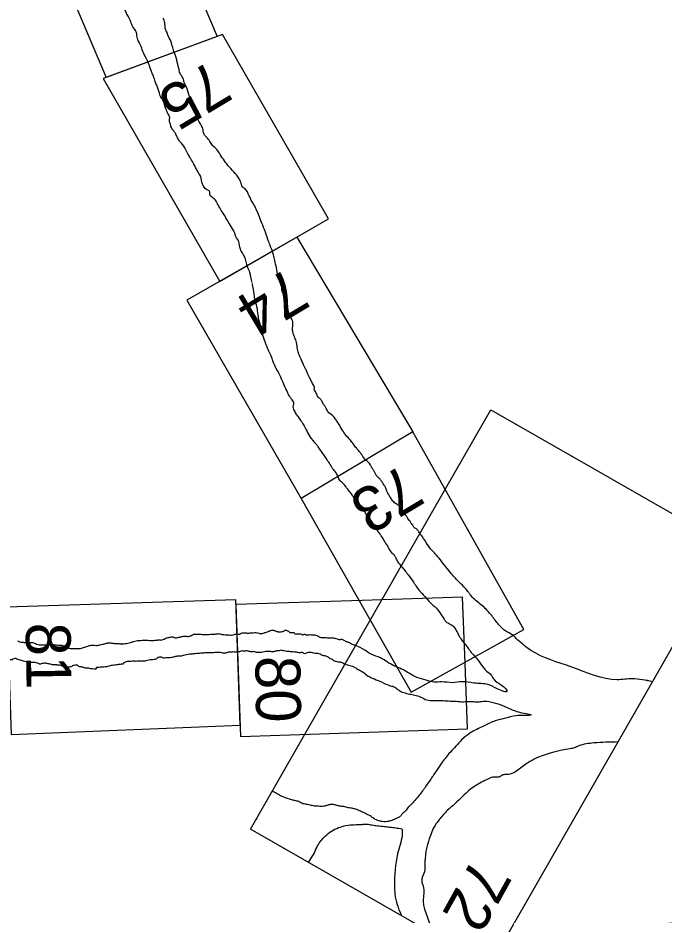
# Model space of a CAD drawing. Extents: x 3930721 to 3950824, y 220441 to 242861.
# Drawn here: x 3935065 to 3935907, y 230142 to 231312 of the extents above; entities that cross this region are included whole.
import ezdxf

# ---------------------------------------------------------------- set-up
doc = ezdxf.new("R2010")
doc.units = 0
doc.layers.add('V-ANNO-NPLT', color=7, linetype='Continuous')
doc.layers.add('V-GRID-MAJR', color=7, linetype='Continuous')

msp = doc.modelspace()

# ---------------------------------------------------------------- linework, layer by layer
at = {"layer": 'V-ANNO-NPLT'}
for p, q in [((3935579.3, 230772), (3935433.9, 230684.9)), ((3935376.4, 230266.9), (3935375.4, 230266.7)), ((3935443.6, 230210.4), (3935451.1, 230222.8))]:
    msp.add_line(p, q, dxfattribs=at)
for points in [[(3935207.9, 231561.8), (3935324.4, 231287.7)], [(3935065.5, 231504.1), (3935179.6, 231234.3)], [(3935331.3, 231290.3), (3935176, 231232.9), (3935327.7, 230968.2)], [(3935469.3, 231049.6), (3935331.3, 231290.3)], [(3935324.4, 231287.7), (3935179.6, 231234.3)], [(3935327.7, 230968.2), (3935469.3, 231049.6)], [(3935428.2, 231026), (3935284.8, 230943.6), (3935433.9, 230684.9)], [(3935428.2, 231026), (3935579.3, 230772)], [(3935681.1, 230800.8), (3935992.7, 230622.2), (3935679.4, 230075.2), (3935367.7, 230253.6)], [(3935622.6, 230698.5), (3935681.1, 230800.8)], [(3935579.3, 230772), (3935433.9, 230684.9), (3935577.3, 230432.3), (3935724.2, 230514.3)], [(3935724.2, 230514.3), (3935579.3, 230772)], [(3935436.6, 230373.8), (3935622.6, 230698.5)], [(3935050.4, 230543.6), (3935348.6, 230553.2)], [(3935354.5, 230389.5), (3935348.6, 230553.2)], [(3935513.5, 230552.1), (3935348.9, 230546.9)], [(3935644.3, 230556.3), (3935513.5, 230552.1)], [(3935647.5, 230470.2), (3935644.3, 230556.3)], [(3935050.4, 230543.6), (3935056, 230377.1), (3935354.5, 230389.5)], [(3935348.9, 230546.9), (3935355, 230374.6), (3935650.8, 230384.6), (3935647.5, 230470.2)], [(3935367.7, 230253.6), (3935436.6, 230373.8)]]:
    msp.add_lwpolyline(points, dxfattribs=at)
for points in [[(3935247.5, 231218.9), (3935243.8, 231229), (3935241.4, 231236), (3935239.2, 231240.8), (3935236, 231249.9), (3935231.5, 231260.2), (3935227.6, 231268.1), (3935224.5, 231276.5), (3935221.6, 231281.8), (3935219.9, 231288.4), (3935218.9, 231293.5), (3935214.7, 231300.1), (3935211.7, 231306.9), (3935208.3, 231314), (3935205.3, 231319.9), (3935201.5, 231328.1), (3935199.8, 231331.7), (3935196.4, 231337.4)], [(3935253.6, 231311.8), (3935255.7, 231305.8), (3935256, 231301.6), (3935257.1, 231296.5), (3935259.3, 231291.6)], [(3935271.5, 231258.5), (3935267.1, 231271.3), (3935264.7, 231279.3), (3935261.1, 231287.6), (3935259.3, 231291.6)], [(3935328.2, 231133.7), (3935324.1, 231140), (3935318.4, 231145.4), (3935315, 231150.7), (3935310.3, 231156.3), (3935307.4, 231159.6), (3935306.1, 231165.7), (3935305.1, 231168.7), (3935299.8, 231178.8), (3935296.1, 231188.3), (3935294.6, 231193.2), (3935291.8, 231199.4), (3935288.7, 231207.7), (3935287, 231213.2), (3935282.8, 231225), (3935281.1, 231228.4), (3935280.5, 231232.1), (3935276.7, 231238), (3935274.7, 231244.8), (3935272.4, 231253.9), (3935271.5, 231258.5)], [(3935302.9, 231105.2), (3935298.5, 231112.7), (3935294.1, 231121), (3935290.1, 231127.9), (3935287.3, 231132.8), (3935283.5, 231139.9), (3935277.7, 231148.6), (3935274.8, 231152), (3935272.2, 231156.4), (3935269.9, 231161.4), (3935265.5, 231167.6), (3935264.2, 231170.1), (3935263.1, 231174.4), (3935262.1, 231178.2), (3935262.5, 231181.6), (3935260.1, 231187.1), (3935258.2, 231191.4), (3935255.7, 231199.4), (3935254.5, 231203.4), (3935251.8, 231207.1), (3935249.3, 231213.8), (3935247.5, 231218.9)], [(3935396.3, 231007.8), (3935390.6, 231022.7), (3935386, 231035.7), (3935381.5, 231047), (3935377.3, 231058.1), (3935370.8, 231070.6), (3935366.1, 231079.9), (3935360.3, 231089.2), (3935357.4, 231091.5), (3935355.2, 231097.7), (3935353.6, 231101.3), (3935347.9, 231109), (3935340.1, 231117.5), (3935328.2, 231133.7)], [(3935370.1, 230966.6), (3935368.2, 230974.2), (3935367.1, 230979.7), (3935363.9, 230987), (3935360.2, 231000.5), (3935354.7, 231010.3), (3935352.5, 231020.2), (3935348.9, 231026.7), (3935347.3, 231031.3), (3935345.9, 231034.3), (3935340.3, 231043.1), (3935335.9, 231051.1), (3935330.9, 231058.9), (3935326.7, 231066.2), (3935323.1, 231072.7), (3935318.4, 231077.6), (3935314.8, 231081.4), (3935315, 231084.5), (3935313.9, 231086.3), (3935310.7, 231088.2), (3935302.9, 231105.2)], [(3935438.1, 230856.9), (3935433.7, 230866.7), (3935431, 230873.4), (3935429.1, 230879.6), (3935427.8, 230888.6), (3935425.5, 230895), (3935422.9, 230902.7), (3935422.9, 230909.4), (3935422.5, 230917.3), (3935419, 230923.5), (3935416.4, 230933.7), (3935413.5, 230942.6), (3935412.1, 230950.6), (3935409.6, 230954.1), (3935408.7, 230960.3), (3935403.7, 230975.1), (3935401.6, 230986.1), (3935399.5, 230995.5), (3935397.7, 231002.7), (3935396.3, 231007.8)], [(3935416.9, 230821.7), (3935409.5, 230838.2), (3935404.9, 230848.5), (3935400.4, 230856.4), (3935396.7, 230865.7), (3935393.4, 230873.8), (3935390, 230881), (3935387.9, 230886.8), (3935384.5, 230896.6), (3935381.3, 230909.2), (3935377.7, 230924.6), (3935376.3, 230935.2), (3935373.3, 230945.6), (3935372.5, 230952.8), (3935370.8, 230962), (3935370.3, 230965.4)], [(3935505.8, 230750.9), (3935502, 230755.8), (3935498, 230761.2), (3935492.1, 230767.7), (3935487.4, 230774.7), (3935482.3, 230783.2), (3935479.4, 230787.5), (3935476.1, 230792), (3935470.1, 230796.9), (3935465.6, 230804.2), (3935461.7, 230810.4), (3935459.4, 230814.3), (3935456, 230817.2), (3935453.6, 230822.4), (3935451, 230827.4), (3935451.2, 230829.8), (3935448.8, 230835), (3935446.3, 230839.9), (3935443.1, 230846.1), (3935441.2, 230850.6), (3935439.3, 230854.7), (3935438.1, 230856.9)], [(3935434.8, 230784.9), (3935433.8, 230786.4), (3935430.4, 230791.4), (3935427.1, 230795.9), (3935424.4, 230801.3), (3935423.6, 230804.8), (3935424.5, 230808.5), (3935422.1, 230813.7), (3935419.4, 230817), (3935416.9, 230821.7)], [(3935434.8, 230784.9), (3935440.4, 230774.4), (3935445.1, 230766), (3935453.7, 230755.5)], [(3935481.9, 230713.7), (3935479.3, 230718.6), (3935475.9, 230722.7), (3935471.8, 230729.4), (3935467.7, 230735.3), (3935464.2, 230740.7), (3935460.3, 230746.4), (3935455.9, 230752.5), (3935453.8, 230755.4), (3935453.7, 230755.5)], [(3935588.6, 230639.2), (3935587.2, 230641.5), (3935585.1, 230644.4), (3935583.1, 230646), (3935581.2, 230647.1), (3935579.2, 230650.1), (3935577.5, 230652.3), (3935575.3, 230655.7), (3935573.4, 230658.2), (3935571.1, 230662.1), (3935568.6, 230664.4), (3935565.8, 230669.5), (3935563.5, 230672.1), (3935560.7, 230675.9), (3935556.8, 230678.6), (3935552.6, 230682.9), (3935549.6, 230687.2), (3935546.9, 230691.8), (3935545, 230695.8), (3935543.8, 230699.5), (3935541.2, 230703.6), (3935538.6, 230707.7), (3935535.9, 230711), (3935533.1, 230713.5), (3935530.9, 230717), (3935528.9, 230720.7), (3935526.7, 230724.1), (3935524.4, 230728.1), (3935520.9, 230732.7), (3935516.7, 230736.5), (3935512.2, 230743), (3935509, 230747), (3935505.8, 230750.9)], [(3935564.3, 230596.9), (3935558.8, 230604.6), (3935556.1, 230610), (3935551.4, 230615), (3935547.4, 230621.6), (3935542.8, 230629), (3935538.3, 230636.3), (3935535.5, 230640.1), (3935530.7, 230647.7), (3935526.7, 230653.8), (3935523, 230659), (3935519.4, 230662.9), (3935517, 230667.3), (3935514.8, 230671.5), (3935513, 230674.8), (3935508.7, 230676.9), (3935506.4, 230680.8), (3935503.7, 230684.1), (3935501.5, 230687.5), (3935498.7, 230692.1), (3935494.5, 230697.2), (3935489, 230704.3), (3935484.6, 230708.2), (3935481.9, 230713.7)], [(3935716.3, 230500.1), (3935708.8, 230507.3), (3935700.8, 230512), (3935691.4, 230520.4), (3935682.2, 230532.2), (3935670.6, 230544.5), (3935656.9, 230556.3), (3935647.7, 230568.1), (3935640.2, 230575.3), (3935629.8, 230586.8), (3935622.6, 230595.7), (3935615.4, 230604.9), (3935608.6, 230613), (3935604.8, 230617.1), (3935598.1, 230625.6), (3935593.5, 230632.9), (3935588.6, 230639.2)], [(3935564.3, 230596.9), (3935573.3, 230585.5), (3935580.2, 230575.9), (3935589, 230563.5), (3935596.9, 230555.2), (3935603.8, 230547.4), (3935608.4, 230543.5), (3935614.4, 230536.4), (3935620.2, 230527.5), (3935622.7, 230524.2), (3935627.2, 230521.7), (3935632.8, 230517.5), (3935637.5, 230510.2), (3935639.9, 230505.2), (3935644.3, 230498.9), (3935651.9, 230489), (3935656.7, 230482.8), (3935663.4, 230475.3), (3935670.9, 230465), (3935677, 230458.6), (3935677.9, 230458.1), (3935685, 230449.3), (3935693.6, 230442.5), (3935699.2, 230438.2), (3935702, 230433.8), (3935689.3, 230436.9), (3935677.2, 230442.3), (3935659, 230444.3), (3935644.1, 230445.9), (3935630.9, 230444.7), (3935617, 230445.8), (3935607, 230445.5), (3935596.7, 230448), (3935584.5, 230451.7), (3935564.8, 230462.6), (3935554.7, 230466.8), (3935546.1, 230471.8), (3935537.4, 230477.1), (3935525.3, 230481.8), (3935516.7, 230487.2), (3935504.6, 230493.6)], [(3935271.4, 230502.9), (3935270.7, 230502.9), (3935269, 230503.3), (3935268.1, 230503.8), (3935265.8, 230504.3), (3935263.2, 230503.9), (3935261.1, 230503.4), (3935258.8, 230503), (3935257.2, 230502.2), (3935255.2, 230501.3), (3935253.1, 230500.8), (3935251.5, 230500), (3935249.8, 230500.2), (3935247.5, 230500.1), (3935245.7, 230500), (3935242.8, 230499.7), (3935240.2, 230499.2), (3935238.2, 230499.2), (3935236.5, 230499.4), (3935232.4, 230499.8), (3935229.7, 230499.6), (3935226.7, 230500)], [(3935279.7, 230504.9), (3935278.1, 230504.4), (3935276, 230504), (3935273.6, 230503.5), (3935271.4, 230502.9)], [(3935288.6, 230505.6), (3935286.4, 230504.6), (3935284.8, 230504.9), (3935282, 230505.1), (3935279.7, 230504.9)], [(3935381.6, 230508.3), (3935381.4, 230508.2), (3935380, 230508.7), (3935378.9, 230509.1), (3935375.3, 230509.6), (3935371.4, 230509.5), (3935368.3, 230509.4), (3935365.8, 230509), (3935363.7, 230509.1), (3935358.8, 230509.3), (3935355.6, 230509), (3935353.2, 230507.7), (3935350.8, 230508), (3935348.5, 230507.7), (3935347.3, 230507.6), (3935344.8, 230506.6), (3935341.7, 230506.5), (3935338.8, 230506.8), (3935331.1, 230507.3), (3935326.2, 230508.3), (3935320.8, 230507.7), (3935317.5, 230507.7), (3935314, 230507.3), (3935307.1, 230507.3), (3935303, 230507.5), (3935299.8, 230507.7), (3935294.5, 230507.6), (3935293, 230507.4), (3935291.4, 230506.1), (3935288.6, 230505.6)], [(3935395, 230512.8), (3935392, 230511.7), (3935389.3, 230510.5), (3935385.2, 230509.3), (3935382.7, 230508.6), (3935381.6, 230508.3)], [(3935418.4, 230510.9), (3935416.8, 230511.8), (3935415.8, 230512.4), (3935414.1, 230513.1), (3935412.8, 230512.8), (3935411.1, 230511.9), (3935409.7, 230511.3), (3935408.6, 230510.9), (3935405.7, 230510.7), (3935404.1, 230510.8), (3935402.7, 230511.3), (3935400.9, 230511.9), (3935399.5, 230512.4), (3935398.1, 230512.7), (3935396.6, 230513.1), (3935395, 230512.8)], [(3935442.7, 230506.8), (3935441.8, 230506.6), (3935440.6, 230506.8), (3935439.4, 230507.2), (3935437.6, 230507.5), (3935437.3, 230507.4), (3935436, 230507.1), (3935435.6, 230506.8), (3935434.7, 230507.6), (3935431.8, 230507.9), (3935429.5, 230508.2), (3935425.4, 230508.7), (3935424.8, 230509.6), (3935423.5, 230509.8), (3935421.5, 230509.7), (3935420.1, 230509.7), (3935419.5, 230510), (3935418.4, 230510.9)], [(3935453.5, 230506.5), (3935451.1, 230506.7), (3935448.3, 230506.7), (3935445.2, 230507), (3935442.7, 230506.8)], [(3935504.6, 230493.6), (3935499.4, 230495.2), (3935496.9, 230496.6), (3935495, 230497.5), (3935493.1, 230498.1), (3935491.5, 230499.1), (3935489.7, 230499.8), (3935488, 230500.6), (3935485.7, 230500.9), (3935483.6, 230500.7), (3935481.1, 230501.7), (3935478.2, 230502.3), (3935476.2, 230502.7), (3935473.2, 230502.8), (3935470.8, 230502.9), (3935469.1, 230502.8), (3935466, 230503.2), (3935463.8, 230503.2), (3935458.5, 230503.6), (3935455.5, 230505.4), (3935453.5, 230506.5)], [(3935138.4, 230488.8), (3935134.3, 230488.9), (3935130.1, 230489.7), (3935127.3, 230490.5), (3935123.4, 230492.8), (3935118.7, 230493.3), (3935115.1, 230493.6), (3935112.9, 230493.8), (3935109, 230494.1), (3935103, 230493.5), (3935099.9, 230493.7), (3935096.5, 230493.9), (3935093, 230493.9), (3935089, 230494.6), (3935086, 230496.1), (3935082.6, 230496.7), (3935079.4, 230496.8), (3935076.1, 230497), (3935073.3, 230496.9), (3935070.5, 230497.1), (3935067.1, 230497.7), (3935065.3, 230498.7), (3935064.8, 230498.8)], [(3935199.6, 230495.3), (3935198.9, 230495.2), (3935194.4, 230495.6), (3935192, 230495.5), (3935186.3, 230496.3), (3935181.6, 230496.2), (3935177.1, 230495.1), (3935171.5, 230493.7), (3935166.4, 230492.9), (3935162.8, 230493.3), (3935158.5, 230493), (3935154.3, 230491.4), (3935151, 230490.7), (3935145.9, 230489.1), (3935142, 230489), (3935140.2, 230488.9), (3935138.4, 230488.8)], [(3935212.4, 230497.2), (3935209.9, 230496.3), (3935206.2, 230495.5), (3935202.8, 230495), (3935200.7, 230494.9), (3935199.5, 230495.3)], [(3935226.7, 230500), (3935223.3, 230499.2), (3935220.7, 230499.3), (3935217, 230498.5), (3935213.9, 230497.7), (3935212.4, 230497.2)], [(3935891.9, 230445.9), (3935865.5, 230449.8), (3935845.7, 230448.6), (3935786.8, 230465), (3935733.4, 230486.8), (3935716.3, 230500.1)], [(3935891.8, 230446), (3935865.5, 230449.8), (3935845.7, 230448.6), (3935786.8, 230465), (3935733.4, 230486.8), (3935716.3, 230500.1)], [(3935306.6, 230483.2), (3935299.7, 230482.9), (3935295.6, 230482.4), (3935293.1, 230482.2), (3935288.3, 230481.9), (3935284.5, 230480.9), (3935280.4, 230480.4), (3935278.6, 230479.8), (3935273.6, 230479.3), (3935269, 230478.5), (3935264.9, 230477.4), (3935261.2, 230477.1), (3935257.7, 230477.1), (3935254.3, 230476.8), (3935252.7, 230477.5), (3935248.9, 230478), (3935246.3, 230476.6), (3935242.3, 230474.9), (3935238.9, 230474.6), (3935235.2, 230474.2), (3935231.4, 230473.2), (3935226.3, 230473), (3935221.8, 230472.8), (3935218.2, 230472.6), (3935213.6, 230472.8), (3935210.1, 230472.2), (3935207, 230472.4), (3935204.4, 230471.5)], [(3935399.8, 230485.6), (3935395.9, 230485), (3935394.3, 230485.4), (3935392.5, 230485.3), (3935389.5, 230485.6), (3935387.7, 230485.5), (3935383.9, 230484.6), (3935377.5, 230484), (3935375.5, 230484.1), (3935373.5, 230485.2), (3935371, 230485), (3935367.9, 230485.1), (3935365.8, 230485.5), (3935363.7, 230486.4), (3935360.8, 230485.9), (3935358.7, 230485.9), (3935356.8, 230486.1), (3935353.3, 230485.1), (3935350.2, 230484.8), (3935348.1, 230484.7), (3935344.9, 230484.8), (3935343.1, 230484.7), (3935338.8, 230484.4), (3935334.6, 230483.1), (3935330.6, 230483.7), (3935326.5, 230484.2), (3935321.4, 230484), (3935318, 230483.7), (3935313.3, 230483.6), (3935309, 230483.8), (3935306.6, 230483.2)], [(3935490.8, 230468.9), (3935488.2, 230470.2), (3935484.5, 230471.5), (3935482.3, 230471.7), (3935479.7, 230472.3), (3935477.6, 230472.7), (3935475.6, 230474.2), (3935473.4, 230475.5), (3935471.2, 230476.5), (3935468.3, 230478.6), (3935466.2, 230479.5), (3935464.1, 230479.9), (3935461.6, 230480.2), (3935458.5, 230481.8), (3935455.4, 230483), (3935452.2, 230482.9), (3935448.9, 230483.7), (3935445.3, 230484.1), (3935442.9, 230484.1), (3935440.2, 230483.4), (3935438.5, 230482.6), (3935436.5, 230483.5), (3935434.8, 230484.2), (3935432.9, 230483.9), (3935431.1, 230483.8), (3935429, 230484.2), (3935426.5, 230484.5), (3935423.5, 230484.8), (3935421.5, 230484.9), (3935418.8, 230485.3), (3935411.7, 230486.1), (3935406.4, 230486.9), (3935403.8, 230486.1), (3935401.9, 230486.3), (3935399.8, 230485.6)], [(3935114.6, 230468), (3935110.4, 230468), (3935106.3, 230469), (3935101.8, 230469.9), (3935097.4, 230469.9), (3935092.9, 230469.1), (3935090.1, 230470.4), (3935084.3, 230471), (3935080.4, 230471.3), (3935075.4, 230471.9), (3935072.1, 230472.7), (3935066.5, 230474.6), (3935063.3, 230475.6), (3935060.5, 230476.4), (3935058.2, 230475.4), (3935056.1, 230474.4), (3935054.3, 230474.8), (3935053.5, 230475)], [(3935204.4, 230471.5), (3935202.8, 230470.5), (3935202.2, 230469.6), (3935197.9, 230468.7), (3935193.3, 230467.9), (3935186.3, 230467.1), (3935180.5, 230465.6), (3935171.8, 230464.9), (3935168.8, 230464.7), (3935167.2, 230464.5), (3935166.6, 230463.6), (3935166.6, 230463), (3935164, 230462.6), (3935160.3, 230462.7), (3935155.9, 230463.9), (3935152.4, 230463.9), (3935148.2, 230465.2), (3935144.2, 230465.9), (3935142.2, 230467.4), (3935138.8, 230467.6), (3935135.9, 230466.7), (3935133.7, 230465.4), (3935131, 230464.9), (3935126.7, 230465.5), (3935122.6, 230466.5), (3935118.8, 230467.5), (3935116, 230467.8), (3935114.6, 230468)], [(3935490.8, 230468.9), (3935503.8, 230464.7), (3935508.5, 230461.9), (3935514.5, 230458.4), (3935521.4, 230453.3), (3935525.6, 230451.2), (3935529.4, 230449.6), (3935538.6, 230445.7), (3935550, 230440.8), (3935556.1, 230438.9), (3935560.4, 230435.5), (3935575.1, 230430), (3935581.8, 230428.7), (3935589.9, 230426), (3935597.6, 230422.2), (3935606.2, 230421.6), (3935611.7, 230421.6), (3935618.7, 230421.4), (3935628.1, 230420.8), (3935636.3, 230420.6), (3935642.9, 230419.9), (3935652.4, 230420.3), (3935660.3, 230420), (3935666.2, 230420), (3935672.5, 230420.8), (3935685.5, 230418.4), (3935698.4, 230414.3), (3935706.1, 230410.6), (3935717.3, 230406.6), (3935727.2, 230404.6), (3935733.8, 230402.9), (3935723.9, 230401.8), (3935713.9, 230401.7), (3935698.6, 230398), (3935686.9, 230395), (3935672.2, 230388.5), (3935653.8, 230378.8), (3935643.4, 230370.5), (3935635.5, 230361.8), (3935628.3, 230354.3), (3935617.6, 230340.9), (3935610.6, 230330.7), (3935602.8, 230319.1), (3935595.4, 230308.2), (3935586.5, 230296.4), (3935580.4, 230289.2), (3935576.7, 230285.4)], [(3935846.8, 230367.5), (3935815.4, 230366.1), (3935795.6, 230362.2), (3935790, 230359.8), (3935784.1, 230358.5), (3935743.2, 230347.4), (3935732.1, 230341.9), (3935718.1, 230332.1), (3935702.1, 230324.8), (3935696.7, 230324.5), (3935691.3, 230321.5), (3935686.1, 230321.6), (3935675.6, 230318.2), (3935658.5, 230308.7), (3935633.7, 230286.3), (3935624.3, 230278), (3935613.9, 230266.1), (3935608.3, 230258.6), (3935600.8, 230240.9), (3935596.8, 230226.8), (3935595.6, 230216.3), (3935595.1, 230211), (3935594.4, 230197.9), (3935591, 230185.8), (3935592.8, 230179.7), (3935593, 230159.6), (3935603.6, 230119.7), (3935603.7, 230118.5)], [(3935402.8, 230299.6), (3935400.4, 230300.9), (3935398.9, 230301.8), (3935396.2, 230303.2)], [(3935455.2, 230283.5), (3935451.2, 230283.9), (3935445.6, 230285), (3935442.2, 230285.8), (3935439.4, 230286.3), (3935436.2, 230286.9), (3935431, 230289.6), (3935425.5, 230290.9), (3935421.7, 230292), (3935418.5, 230292.8), (3935410.5, 230296), (3935405.6, 230297.9), (3935402.8, 230299.6)], [(3935507.8, 230278.5), (3935504.7, 230279.8), (3935500.2, 230280.9), (3935496.6, 230281.5), (3935493.9, 230281.9), (3935490.8, 230282.8), (3935485.4, 230283.5), (3935480.9, 230284.5), (3935475.9, 230285.7), (3935471.8, 230285.8), (3935467.5, 230284.5), (3935463.4, 230283.6), (3935459.7, 230283.3), (3935456.6, 230283.6), (3935455.2, 230283.5)], [(3935576.7, 230285.4), (3935573.4, 230282.3), (3935569.6, 230277.3), (3935568.3, 230276.2), (3935565.7, 230273.7), (3935563.4, 230270.8), (3935559.6, 230268.4), (3935556, 230266.6), (3935551.9, 230265), (3935547.6, 230263.9), (3935543.9, 230263.3), (3935539.6, 230263.6), (3935534, 230265.2), (3935530.5, 230266.5), (3935526.4, 230269.1), (3935520.7, 230272.6), (3935517.6, 230274.2), (3935511, 230277.2), (3935507.8, 230278.5)], [(3935451.1, 230222.8), (3935455.3, 230232.1), (3935465.2, 230244.7), (3935473.5, 230251.2), (3935492.3, 230258.4), (3935513.9, 230259.7)], [(3935565.6, 230253.6), (3935556.8, 230255.1), (3935549.6, 230256), (3935541.7, 230256.8), (3935533.6, 230257.8), (3935526.5, 230258.8), (3935520, 230259.8), (3935513.9, 230259.7)], [(3935565.6, 230253.6), (3935565.3, 230245.4), (3935559.6, 230221.6), (3935555.5, 230180.1), (3935556, 230169.1), (3935564.3, 230142.1), (3935564.4, 230141.9)]]:
    msp.add_spline(points, degree=3, dxfattribs=at)
at = {"layer": 'V-GRID-MAJR'}
msp.add_spline([(3935736.6, 230127.9), (3940756.9, 230218.1), (3946078.3, 230314.5), (3946614.6, 230324.3)], degree=3, dxfattribs=at)

# ---------------------------------------------------------------- texts
at = {"layer": 'V-ANNO-NPLT'}
for s, rotation, p in [('75', 210.9116, (3935317.4, 231258)), ('74', 210.9116, (3935418.4, 230987.7)), ('73', 210.9116, (3935567.9, 230731.3)), ('81', 270.9116, (3935074.7, 230522.8)), ('80', 270.9116, (3935374, 230479.3)), ('72', 240.9116, (3935658.8, 230219.1))]:
    msp.add_text(s, height=58.5, rotation=rotation, dxfattribs=at).set_placement(p)

doc.saveas('drawing.dxf')
